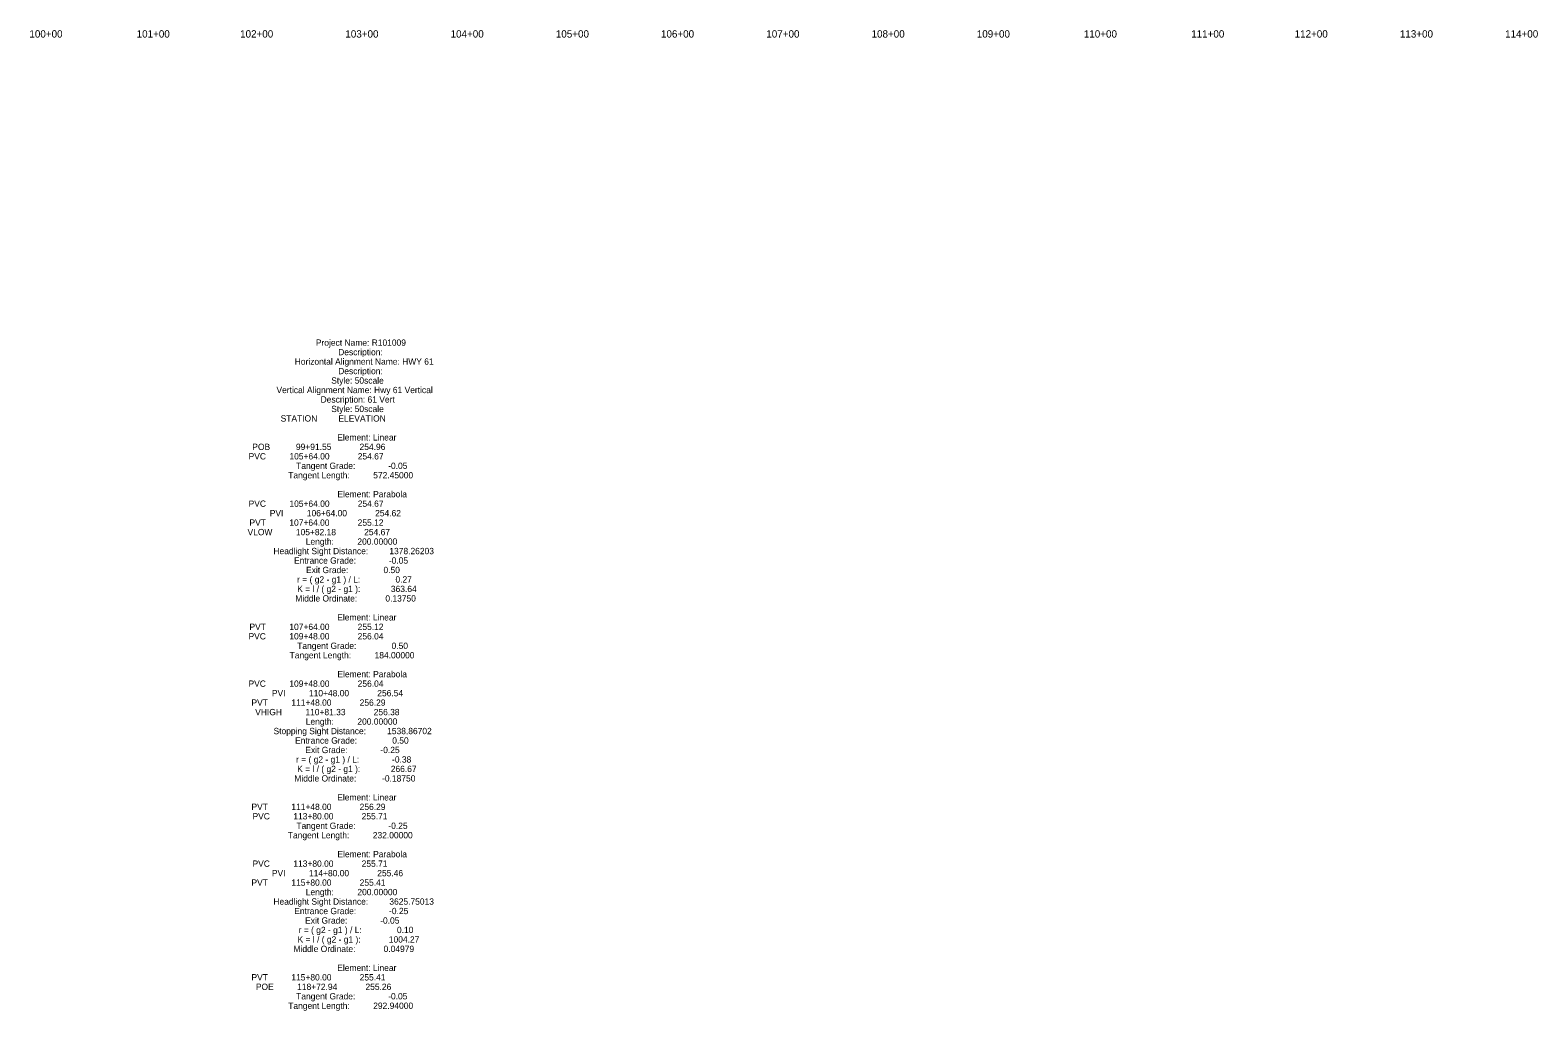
# Model space of a CAD drawing. Extents: x 1930770 to 1938778, y 596900 to 600561.
# Drawn here: x 1932379 to 1933811, y 597640 to 598572 of the extents above; entities that cross this region are included whole.
import ezdxf

# ---------------------------------------------------------------- set-up
doc = ezdxf.new("R2010")
doc.units = 0
doc.layers.add('S_CROSS_DRAIN_ANNOT', color=7, linetype='Continuous')
doc.layers.add('S_DROP_INLET_ANNOT', color=7, linetype='Continuous')

msp = doc.modelspace()

# ---------------------------------------------------------------- texts
at = {"layer": 'S_CROSS_DRAIN_ANNOT'}
for s, p in [('             Project Name: R101009', (1932621.2, 598271.8)), ('              Description: ', (1932640.2, 598262.8)), ('Horizontal Alignment Name: HWY 61', (1932630.1, 598253.8)), ('              Description: ', (1932640.2, 598244.8)), ('                    Style: 50scale', (1932620.2, 598235.8)), ('  Vertical Alignment Name: Hwy 61 Vertical', (1932608.3, 598226.8)), ('              Description: 61 Vert', (1932623.5, 598217.8)), ('                    Style: 50scale', (1932620.2, 598208.8)), ('                                       STATION         ELEVATION', (1932529.8, 598199.8)), ('                        POB           99+91.55            254.96', (1932536.3, 598172.8)), ('Element: Linear  ', (1932670.5, 598181.8)), ('                        PVC          105+64.00            254.67', (1932532.8, 598163.8)), ('            Tangent Length:          572.45000', (1932597.2, 598145.8)), ('             Tangent Grade:              -0.05', (1932602.5, 598154.8)), ('                        PVC          105+64.00            254.67', (1932532.8, 598118.8)), ('Element: Parabola', (1932670.7, 598127.8)), ('                        PVT          107+64.00            255.12', (1932533.6, 598100.8)), ('                        PVI          106+64.00            254.62', (1932552.9, 598109.8)), ('                       VLOW          105+82.18            254.67', (1932534, 598091.8)), ('  Headlight Sight Distance:         1378.26203', (1932605.4, 598073.8)), ('                    Length:          200.00000', (1932596, 598082.8)), ('            Entrance Grade:              -0.05', (1932602.7, 598064.8)), ('       r = ( g2 - g1 ) / L:               0.27', (1932616.8, 598046.8)), ('                Exit Grade:               0.50', (1932605.2, 598055.8)), ('           Middle Ordinate:            0.13750', (1932606.1, 598028.8)), ('       K = l / ( g2 - g1 ):             363.64', (1932616.9, 598037.8)), ('                        PVT          107+64.00            255.12', (1932533.6, 598001.8)), ('Element: Linear  ', (1932670.5, 598010.8)), ('                        PVC          109+48.00            256.04', (1932532.7, 597992.8)), ('            Tangent Length:          184.00000', (1932598.5, 597974.8)), ('             Tangent Grade:               0.50', (1932603.5, 597983.8)), ('                        PVC          109+48.00            256.04', (1932532.7, 597947.8)), ('Element: Parabola', (1932670.7, 597956.8)), ('                        PVT          111+48.00            256.29', (1932535.5, 597929.8)), ('                        PVI          110+48.00            256.54', (1932554.9, 597938.8)), ('                      VHIGH          110+81.33            256.38', (1932543.5, 597920.8)), ('   Stopping Sight Distance:         1538.86702', (1932603.3, 597902.8)), ('                    Length:          200.00000', (1932596, 597911.8)), ('            Entrance Grade:               0.50', (1932603.7, 597893.8)), ('       r = ( g2 - g1 ) / L:              -0.38', (1932615.8, 597875.8)), ('                Exit Grade:              -0.25', (1932604.5, 597884.8)), ('           Middle Ordinate:           -0.18750', (1932605.2, 597857.8)), ('       K = l / ( g2 - g1 ):             266.67', (1932616.8, 597866.8)), ('                        PVT          111+48.00            256.29', (1932535.5, 597830.8)), ('Element: Linear  ', (1932670.5, 597839.8)), ('                        PVC          113+80.00            255.71', (1932536.5, 597821.8)), ('            Tangent Length:          232.00000', (1932596.8, 597803.8)), ('             Tangent Grade:              -0.25', (1932602.7, 597812.8)), ('Element: Parabola', (1932670.7, 597785.8)), ('                        PVC          113+80.00            255.71', (1932536.5, 597776.8)), ('                        PVT          115+80.00            255.41', (1932535.5, 597758.8)), ('                        PVI          114+80.00            255.46', (1932554.9, 597767.8)), ('                    Length:          200.00000', (1932596, 597749.8)), ('  Headlight Sight Distance:         3625.75013', (1932605.4, 597740.8)), ('            Entrance Grade:              -0.25', (1932602.9, 597731.8)), ('       r = ( g2 - g1 ) / L:               0.10', (1932618.2, 597713.8)), ('                Exit Grade:              -0.05', (1932604.3, 597722.8)), ('       K = l / ( g2 - g1 ):            1004.27', (1932617.2, 597704.8)), ('           Middle Ordinate:            0.04979', (1932604.4, 597695.8)), ('Element: Linear  ', (1932670.5, 597677.8)), ('                        PVT          115+80.00            255.41', (1932535.5, 597668.8)), ('                        POE          118+72.94            255.26', (1932539.7, 597659.8)), ('             Tangent Grade:              -0.05', (1932602.5, 597650.8)), ('            Tangent Length:          292.94000', (1932597.2, 597641.8))]:
    msp.add_text(s, height=6, dxfattribs=at).set_placement(p)
at = {"layer": 'S_DROP_INLET_ANNOT'}
for s, p in [('100+00', (1932378, 598564.6)), ('101+00', (1932479.9, 598564.6)), ('102+00', (1932578.2, 598564.6)), ('103+00', (1932678.2, 598564.6)), ('104+00', (1932778.2, 598564.6)), ('105+00', (1932878.2, 598564.6)), ('106+00', (1932978.1, 598564.6)), ('107+00', (1933078.2, 598564.6)), ('108+00', (1933178.2, 598564.6)), ('109+00', (1933278.2, 598564.6)), ('110+00', (1933379.9, 598564.6)), ('111+00', (1933481.9, 598564.6)), ('112+00', (1933580.2, 598564.6)), ('113+00', (1933680.2, 598564.6)), ('114+00', (1933780.2, 598564.6))]:
    msp.add_text(s, height=7, dxfattribs=at).set_placement(p)

doc.saveas('drawing.dxf')
